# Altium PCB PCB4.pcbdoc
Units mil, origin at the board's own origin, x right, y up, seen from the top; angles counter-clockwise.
Board outline 1779.17 x 1753.12 mil, 2 copper layers (Top Layer, Bottom Layer); 24 components, 31 nets, 113 pads, 26 vias.
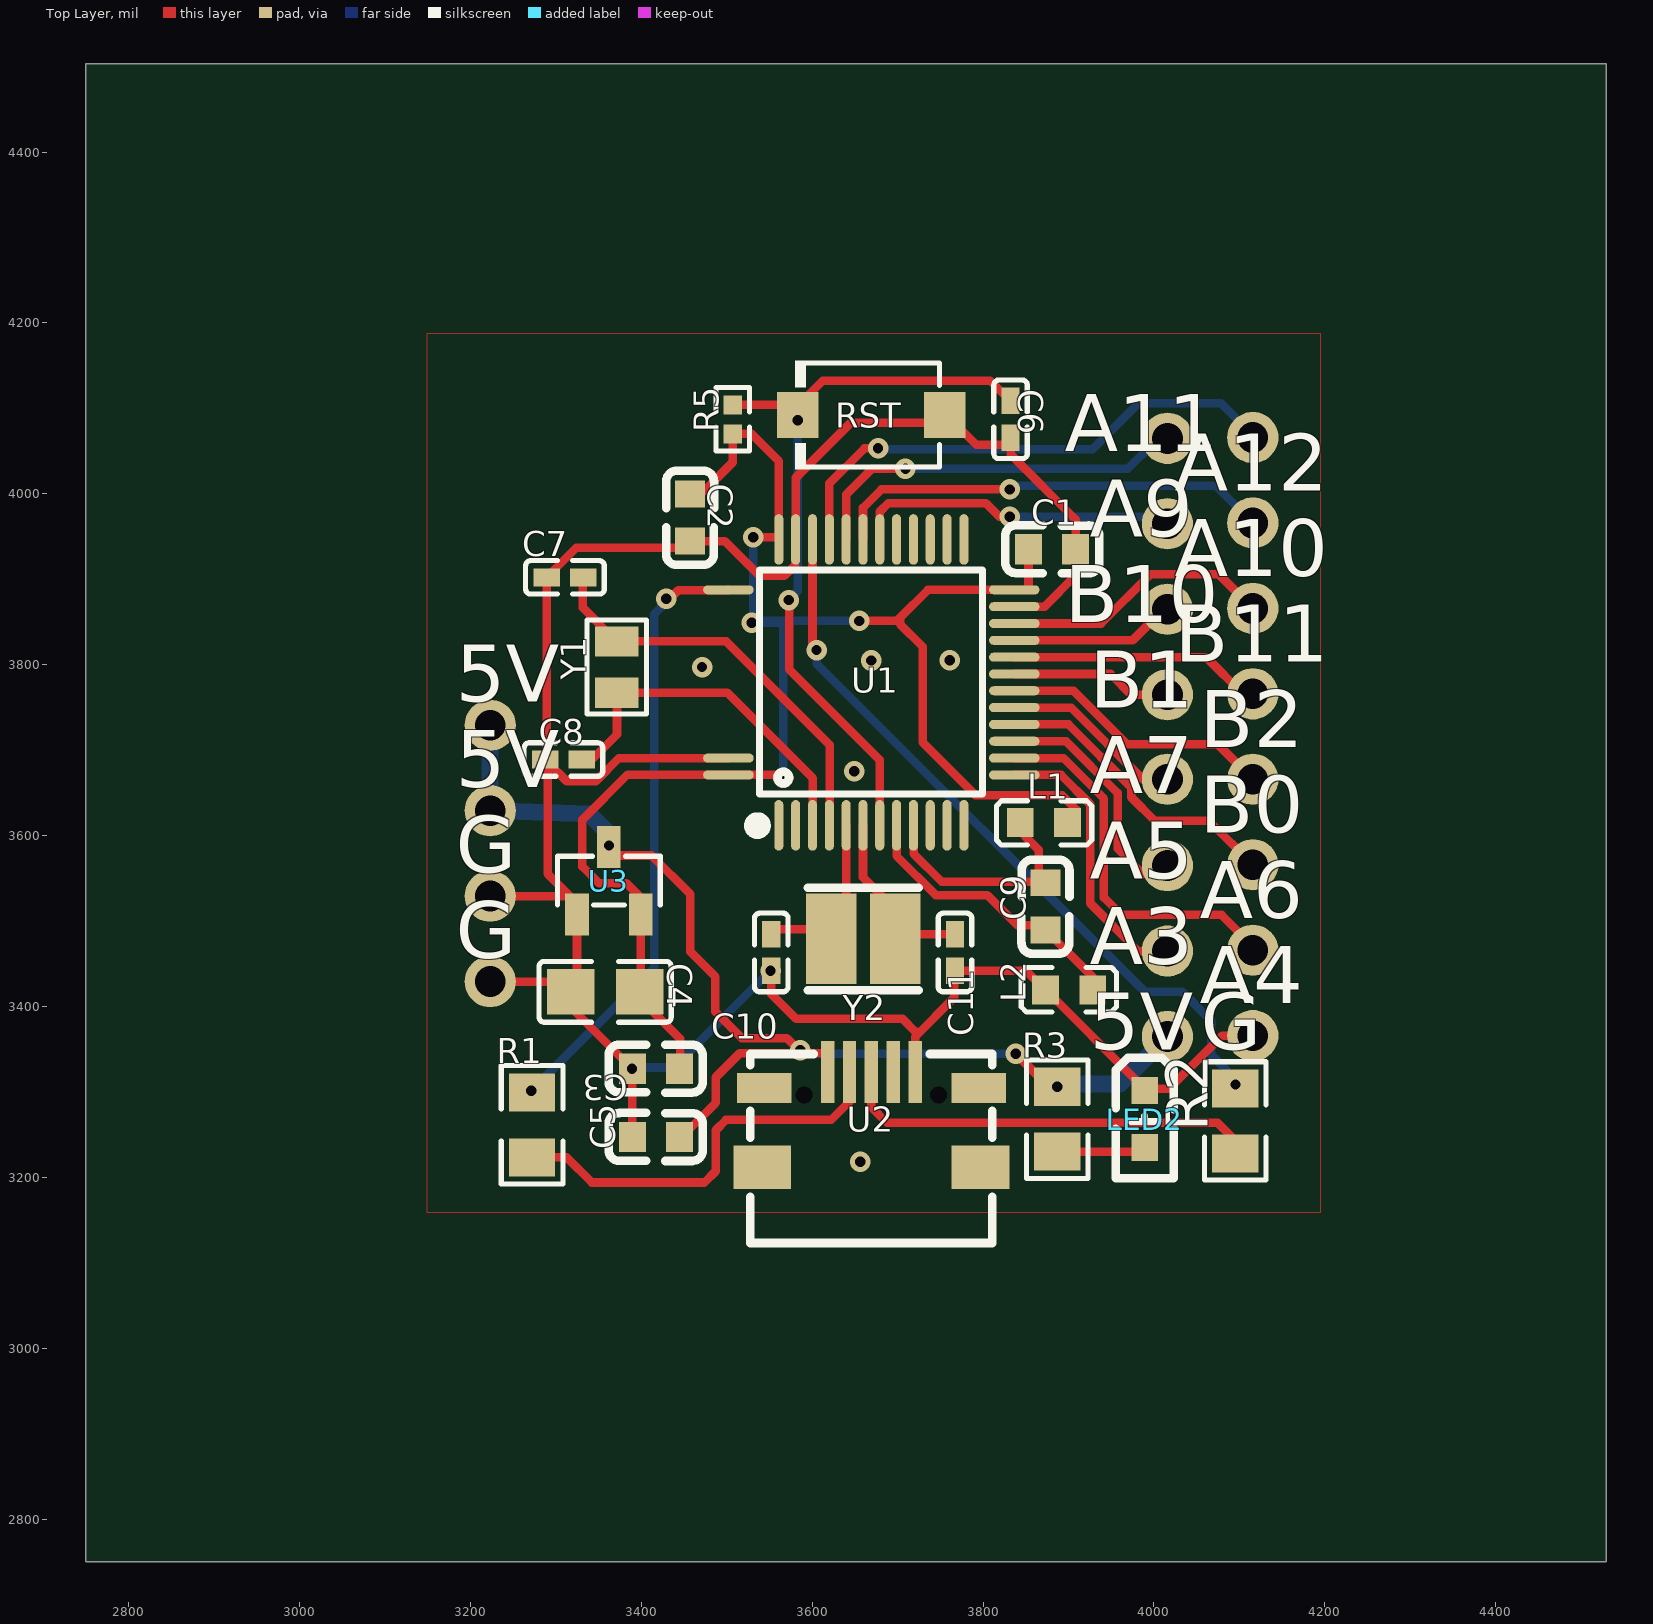
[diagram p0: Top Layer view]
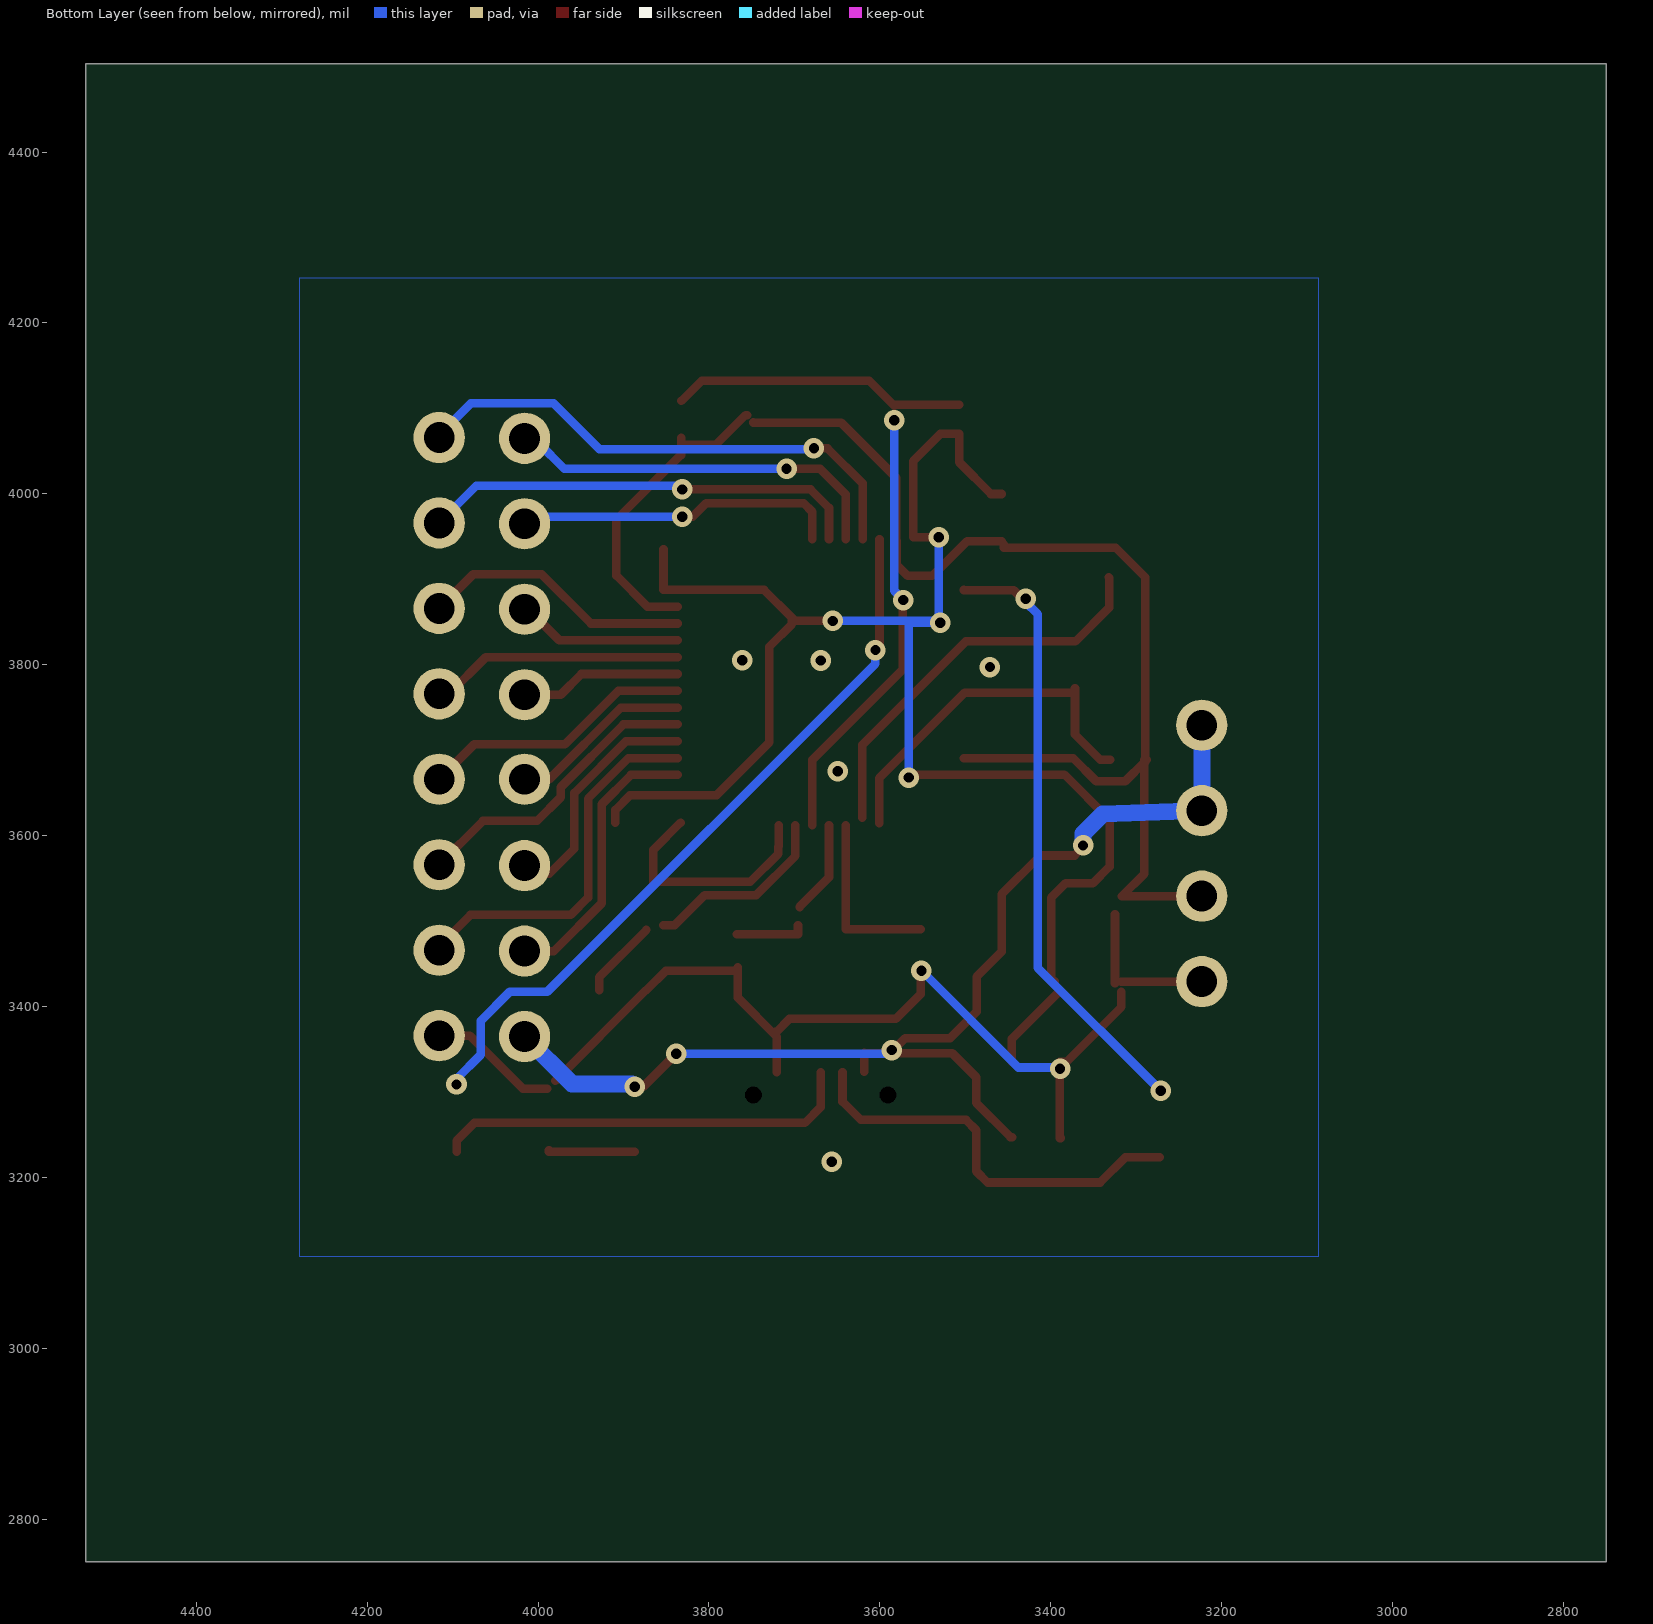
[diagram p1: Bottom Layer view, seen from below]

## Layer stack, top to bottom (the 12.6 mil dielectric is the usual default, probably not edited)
Top Solder: solder mask 0.4, Solder Resist, Dk 3.5
Top Layer: signal copper 1.4
Dielectric 1: dielectric 12.6, FR-4, Dk 4.8
Bottom Layer: signal copper 1.4
Bottom Solder: solder mask 0.4, Solder Resist, Dk 3.5

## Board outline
4529.17,2750 2750,2750 2750,4503.12 4529.17,4503.12

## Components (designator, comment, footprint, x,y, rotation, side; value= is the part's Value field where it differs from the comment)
C1 "" c0603_1 3880.75,3935.15 r180 top
C2 "" c0603_1 3457.15,3972.15 r90 top
C3 "" c0603_1 3417.15,3327.15 r0 top
C4 "" c0805 3357.72,3417.15 r0 top
C5 "" c0603_1 3417.15,3247.15 r0 top
C6 "" c0402_1 3832.15,4087.15 r270 top
C7 "" c0402_1 3310.65,3902.15 r180 top
C8 "" c0402_1 3308.94,3688.98 r180 top
C9 "" c0603_1 3873.15,3517.15 r90 top
C10 "" c0402_1 3552.15,3463.16 r270 top
C11 "" c0402_1 3767.15,3463.16 r270 top
L1 "" l0603 3871.15,3615.15 r180 top
L2 "" l0603 3900.75,3419.15 r0 top
LED2 "" led0603-r-rd_1 3989.24,3268.22 r270 top
R1 "" r0805 3272.15,3261.45 r90 top
R2 "" r0805 4095.18,3266.02 r90 top
R3 "" r0805 3886.79,3268.02 r90 top
R5 "" r0402_1 3507.15,4087.15 r270 top
RST "" sw-smd_l3.9-w3.0-p4.45 3669.28,4092.15 r180 top
U1 "" lqfp-48_l7.0-w7.0-p0.50-ls9.0-bl_4 3669.28,3779.28 r0 top
U2 "" micro-usb-smd_micro-qtzb5.0 3669.28,3267.56 r0 top
U3 "" sot-23-3_l2.9-w1.3-p1.90-ls2.4-br 3362.15,3547.15 r270 top
Y1 "" crystal-smd_l2.0-w1.2 3371.15,3797.15 r90 top
Y2 "" osc-smd_2p-l3.2-w2.5 3659.75,3479.15 r180 top

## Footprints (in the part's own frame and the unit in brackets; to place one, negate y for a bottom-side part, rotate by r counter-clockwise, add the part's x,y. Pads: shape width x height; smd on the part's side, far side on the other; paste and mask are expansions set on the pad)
c0402_1 [mil]
  rect 31.1x21.3 smd: 1(-21.5,0) 2(21.5,0)
  silkscreen extent -46,-20 46,20
c0603_1 [mil]
  rect 31.5x35.4 smd: 1(-27.6,0) 2(27.6,0)
  silkscreen extent -55,-28 55,28
c0805 [mil]
  rect 55.5x53.2 smd: 1(-40.5,0) 2(40.6,0)
  silkscreen extent -77,-36 77,36
crystal-smd_l2.0-w1.2 [mil]
  rect 35.4x51.2 smd: 1(-30,0) 2(30,0)
  silkscreen extent -55,-35 55,35
l0603 [mil]
  rect 31.5x34 smd: 1(-27.6,0) 2(27.6,0)
  silkscreen extent -56,-26 56,26
led0603-r-rd_1 [mil]
  rect 31.5x31.5 smd: 1(33.5,0) 2(-33.5,0)
  silkscreen extent -72,-34 70,34
lqfp-48_l7.0-w7.0-p0.50-ls9.0-bl_4 [mil]
  oval 10.6x59.1 smd: 1(-108.3,-167.3) 2(-88.6,-167.3) 3(-68.9,-167.3) 4(-49.2,-167.3) 5(-29.5,-167.3) 6(-9.8,-167.3) 7(9.8,-167.3) 8(29.5,-167.3) 9(49.2,-167.3) 10(68.9,-167.3) 11(88.6,-167.3) 12(108.3,-167.3) 25(108.3,167.3) 26(88.6,167.3) 27(68.9,167.3) 28(49.2,167.3) 29(29.5,167.3) 30(9.8,167.3) 31(-9.8,167.3) 32(-29.5,167.3) 33(-49.2,167.3) 34(-68.9,167.3) 35(-88.6,167.3) 36(-108.3,167.3)
  oval 59.1x10.6 smd: 13(167.3,-108.3) 14(167.3,-88.6) 15(167.3,-68.9) 16(167.3,-49.2) 17(167.3,-29.5) 18(167.3,-9.8) 19(167.3,9.8) 20(167.3,29.5) 21(167.3,49.2) 22(167.3,68.9) 23(167.3,88.6) 24(167.3,108.3) 37(-167.3,108.3) 47(-167.3,-88.6) 48(-167.3,-108.3)
  silkscreen extent -141,-176 130,132
micro-usb-smd_micro-qtzb5.0 [mil]
  rect 15.7x72.8 smd: 1(-51.2,55.8) 2(-25.6,55.8) 3(0,55.8) 4(25.6,55.8) 5(51.2,55.8)
  rect 67.5x51.2 smd: 6(-127.7,-55.8) 6(127.7,-55.8)
  rect 64x35.4 smd: 6(-125.5,37.1) 6(125.5,37.1)
  Multi-Layer board cut-out: -68.9,28.8 -69.87,33.05 -72.59,36.46 -76.52,38.35 -80.88,38.35 -84.81,36.46 -87.53,33.05 -88.5,28.8 -88.5,28.8 -87.53,24.55 -84.81,21.14 -80.88,19.25 -76.52,19.25 -72.59,21.14 -69.87,24.55 -68.9,28.8
  Multi-Layer board cut-out: 88.5,28.8 87.53,33.05 84.81,36.46 80.88,38.35 76.52,38.35 72.59,36.46 69.87,33.05 68.9,28.8 68.9,28.8 69.87,24.55 72.59,21.14 76.52,19.25 80.88,19.25 84.81,21.14 87.53,24.55 88.5,28.8
  silkscreen extent -142,-144 142,77
osc-smd_2p-l3.2-w2.5 [mil]
  rect 59.1x106.3 smd: 1(37.4,0) 2(-37.4,0)
  silkscreen extent -65,-60 65,60
r0402_1 [mil]
  rect 22.3x21.3 smd: 1(-17,0) 2(17,0)
  silkscreen extent -37,-20 37,20
r0805 [mil]
  rect 44.6x54.2 smd: 1(-38,0) 2(38,0)
  silkscreen extent -69,-36 69,36
sot-23-3_l2.9-w1.3-p1.90-ls2.4-br [mil]
  rect 49.2x27.6 smd: 1(39.4,-37.4) 2(39.4,37.4) 3(-39.4,0)
  silkscreen extent -29,-60 29,60
sw-smd_l3.9-w3.0-p4.45 [mil]
  rect 48.4x53.5 smd: 1(-86,0) 2(86,0)
  silkscreen extent -80,-64 89,64

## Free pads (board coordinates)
  round 60 hole 36: ""(3223.15,3429.15) ""(3223.15,3529.15) ""(3223.15,3629.15) ""(3223.15,3729.15) ""(4015.73,3364.85) ""(4015.73,3464.85) ""(4015.73,3564.85) ""(4015.73,3665.85) ""(4015.73,3764.85) ""(4015.73,3864.85) ""(4015.73,3964.85) ""(4015.73,4064.85) ""(4115.73,3365.85) ""(4115.73,3465.85) ""(4115.73,3565.85) ""(4115.73,3665.85) ""(4115.73,3765.85) ""(4115.73,3865.85) ""(4115.73,3965.85) ""(4115.73,4065.85)

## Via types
v1: diameter 24.02, hole 12.01, Top Layer to Bottom Layer, 26 vias

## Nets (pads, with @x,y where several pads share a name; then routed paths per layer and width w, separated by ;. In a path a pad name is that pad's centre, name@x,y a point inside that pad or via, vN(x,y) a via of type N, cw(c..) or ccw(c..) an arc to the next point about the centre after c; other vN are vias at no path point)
3V3: C1.2 C2.2 C3.2 C4.2 L1.1 R5.2 U1.24 U1.36 U1.48 U3.2 | length 1975.9
  Top Layer w10: C4.2@3390.32,3417.15 3445.34,3362.14 C3.2@3445.34,3335.32 ; C4.2@3395.22,3429.33 3399.55,3429.33 U3.2 3399.55,3527.18 3382.54,3544.19 3350.55,3544.19 3331.08,3563.66 3331.08,3618.56 3383.89,3671.37 3501.58,3671.37 U1.48 3566.18,3670.98 v1(3566.18,3667.88) ; C2.2 3470.03,3999.75 3507.15,4036.87 R5.2@3507.15,4067.26 ; R5.2 3529.15,4070.15 3560.98,4038.32 3560.98,3949.15 v1(3531.15,3949.15) ; v1(3655.15,3851.15) 3699.15,3851.15 3703.15,3855.15 ; C1.2 3853.15,3887.58 U1.24 3735.58,3887.58 3703.15,3855.15 ; L1.1@3909.5,3615.15 3909.5,3630.08 3892.43,3647.15 3791.15,3647.15 3729.15,3709.15 3729.15,3821.15 3703.15,3847.15 3703.15,3855.15
  Bottom Layer w10: v1(3531.15,3949.15) v1@3531.15,3851.15 ; v1(3566.18,3667.88) 3566.18,3849.15 v1(3529.15,3849.15) v1@3531.15,3851.15 ; v1(3655.15,3851.15) v1@3531.15,3851.15
  other v1: 3531.15,3949.15
$3N994: C6.1 R5.1 RST.2 U1.7 | length 868
  Top Layer w10: R5.1 3583.28,4104.15 3583.28,4103.28 3612.15,4132.15 3808.65,4132.15 C6.1 ; v1@3573.17,3873.68 3573.17,3794.38 3679.08,3688.48 U1.7
  Bottom Layer w10: v1(3572.5,3875.6) 3572.5,3875.96 3583.07,3886.53 v1(3583.07,4086.09)
$3N1484: C10.1 U1.5 Y2.1 | length 209.3
  Top Layer w10: C10.1@3552.15,3490.27 3639.78,3490.27 U1.5
$3N1487: C11.1 U1.6 Y2.2 | length 192
  Top Layer w10: U1.6 3659.48,3551.23 3693.81,3516.9 Y2.2@3693.81,3516.12 ; Y2.2@3695.76,3495.15 3695.76,3484.66 C11.1
$3N2325: C7.1 U1.4 Y1.2 | length 476.3
  Top Layer w10: C7.1 3331.72,3901.72 3331.72,3866.58 Y1.2 3499.5,3827.15 3620.65,3706 U1.4@3620.65,3620.89
$3N2326: C8.1 U1.3 Y1.1 | length 431.2
  Top Layer w10: C8.1 3342.17,3688.98 3371.59,3718.39 Y1.1@3371.59,3767.15 ; Y1.1 Y1.1@3371.59,3767.15 ; Y1.1@3371.59,3772.37 Y1.1@3371.59,3767.15 ; U1.3@3600.9,3614.31 3600.9,3666.98 3500.73,3767.15 Y1.1@3371.59,3767.15
$3N4005: R1.1 U2.2 | length 485.3
  Top Layer w10: R1.1 3312.65,3223.45 3342.15,3193.95 3473.95,3193.95 3487.15,3207.15 3487.15,3255.15 3499.15,3267.15 3622.08,3267.15 3643.68,3288.74 U2.2@3643.68,3322.95
$3N4016: R2.1 U2.3 | length 496
  Top Layer w10: U2.3@3669.28,3322.95 3669.28,3282.09 3687.72,3263.65 4074.61,3263.65 4095.18,3243.08 R2.1@4095.18,3230.02
$3N7646: LED2.1 R3.1 | length 102
  Top Layer w10: R3.1 3987.19,3230.02 LED2.1@3987.19,3231.58
+5V: C5.2 pad.@3223.15,3629.15 pad.@3223.15,3729.15 pad.@4015.73,3364.85 R3.2 U2.1 U3.3 | length 1372.6
  Top Layer w10: U3.3 3372.04,3576.66 3412.12,3576.66 3457.48,3531.3 3457.48,3463.99 3486.74,3434.73 3486.74,3393.76 3517.47,3363.03 3570.23,3363.03 v1@3587.74,3345.52 ; C5.2 3447.15,3247.15 3487.15,3287.15 3487.15,3317.15 3515.33,3345.33 v1@3586.03,3345.33 ; U2.1 3618.16,3323.45 3618.16,3345.52 v1@3587.93,3345.33 ; v1@3843.01,3339.9 3876.88,3306.02 v1(3886.79,3306.02) 3887.29,3306.02 R3.2@3887.29,3305.9 ; v1@3586.03,3345.33 v1@3587.74,3345.52 ; v1@3586.03,3345.33 v1@3587.74,3345.33 ; v1@3587.74,3345.33 v1@3587.93,3345.33 ; v1@3587.74,3345.33 v1@3587.93,3345.33 ; v1@3587.74,3345.52 v1@3587.93,3345.33
  Bottom Layer w10: v1@3589.02,3349.05 3589.02,3344.74 v1(3838.34,3344.74)
  Bottom Layer w20: pad.@3223.15,3729.15 3223.15,3629.15 3339.15,3625.15 3362.15,3602.15 v1(3362.15,3588.45) ; v1(3886.79,3306.02) 3889.91,3309.15 3960.03,3309.15 pad.@4015.73,3364.85
  other v1: 3586.03,3349
GND: C1.1 C2.1 C3.1 C4.1 C5.1 C6.2 C7.2 C8.2 C10.2 C11.2 L2.1 LED2.2 pad.@3223.15,3429.15 pad.@3223.15,3529.15 pad.@4115.73,3365.85 RST.1 U1.23 U1.35 U1.47 U2.5 U3.1 | length 3082.5
  Top Layer w10: pad.@3223.15,3429.15 C4.1@3317.22,3429.15 ; pad.@3223.15,3529.15 3316.62,3529.15 3290.36,3555.41 C8.2@3290.36,3685.94 ; C8.2@3290.36,3687.04 C8.2@3290.36,3685.94 ; C4.1 3317.22,3399.48 3381.55,3335.15 3389.28,3335.15 3389.55,3327.14 3389.55,3246.07 C5.1@3388.27,3246.07 ; C4.1@3324.75,3427.38 U3.1 ; C2.1@3455.14,3940.72 3455.14,3937.06 3324.06,3937.06 C7.2 3289.38,3902.15 C8.2@3289.38,3685.94 ; C2.1 3497.87,3944.55 3538.55,3903.88 3567.26,3903.88 3580.38,3916.99 U1.35@3580.38,3945.12 ; U1.47 3373.9,3690.68 3346.81,3663.59 3312.84,3663.59 C8.2@3290.36,3686.06 ; C10.2 3552.15,3414.52 3581.09,3385.58 3705.71,3385.58 3721.07,3370.21 3722.17,3370.21 ; U1.35 3580.68,4018.68 3645.15,4083.15 3747.9,4083.15 RST.1@3747.9,4083.81 ; U2.5@3720.48,3322.95 3720.77,3323.24 3720.77,3364.73 3766.13,3410.09 C11.2@3766.13,3445.93 ; RST.1 3757.15,4092.15 3792.15,4057.15 C6.2@3832.15,4057.15 ; C11.2 3850.64,3441.66 L2.1 3873.51,3419.15 LED2.2@3979.75,3312.91 ; C6.2 C6.2@3832.15,4057.15 ; U1.23 3871.88,3867.88 3908.35,3904.35 C1.1 3908.35,3969.95 3833.15,4045.15 3832.15,4045.15 C6.2@3832.15,4057.15 ; LED2.2@3989.24,3303.72 4017.72,3303.72 4079.85,3365.85 pad.@4115.73,3365.85 ; C8.2@3289.38,3685.94 C8.2@3289.38,3688.98 ; C8.2@3289.38,3685.94 C8.2@3289.38,3687.04 ; C8.2@3289.38,3687.04 C8.2 C8.2@3289.38,3688.98 ; C8.2@3289.38,3687.04 C8.2@3290.36,3686.06 ; C8.2@3289.38,3688.98 3290.36,3688.98 C8.2@3290.36,3685.94 ; C8.2@3290.36,3685.94 C8.2@3290.36,3686.06
  Bottom Layer w10: v1@3393.9,3328.54 3437.98,3328.54 v1(3551.34,3441.9)
  other v1: 3656.11,3218.36 3389,3327.14 3649.15,3675.15 3471.15,3797.15 3669.28,3804.88 3761.15,3805.15
PA3: pad.@4015.73,3464.85 U1.13 | length 332.4
  Top Layer w10: U1.13 3891.23,3670.98 3925.5,3636.71 3925.5,3520.8 3981.45,3464.85 pad.@4015.73,3464.85
PA4: pad.@4115.73,3465.85 U1.14 | length 442.9
  Top Layer w10: U1.14 3894.16,3690.68 3941.5,3643.33 3941.5,3527.43 3961.78,3507.15 4079.15,3507.15 4115.73,3470.57 pad.@4115.73,3465.85
PA5: pad.@4015.73,3564.85 U1.15 | length 291.3
  Top Layer w10: U1.15 3897.09,3710.38 3957.5,3649.96 3957.5,3584.8 3987.15,3555.15 4015.73,3555.15 pad.@4015.73,3564.85
PA6: pad.@4115.73,3565.85 U1.16 | length 354.1
  Top Layer w10: U1.16 3900.01,3730.08 3973.5,3656.59 3973.5,3644.8 4001.15,3617.15 4064.43,3617.15 pad.@4115.73,3565.85
PA7: pad.@4015.73,3665.85 U1.17 | length 213.9
  Top Layer w10: U1.17 3902.94,3749.78 3986.87,3665.85 pad.@4015.73,3665.85
PA9: pad.@4015.73,3964.85 U1.30 | length 371.7
  Top Layer w10: U1.30 3679.08,3979.08 3689.15,3989.15 3803.15,3989.15 3819.15,3973.15 v1(3831.15,3973.15)
  Bottom Layer w10: v1(3831.15,3973.15) pad.@4007.43,3973.15
PA10: pad.@4115.73,3965.85 U1.31 | length 520.9
  Top Layer w10: U1.31 3659.48,3983.48 3681.15,4005.15 v1@3829.15,4005.15
  Bottom Layer w10: v1(3831.15,4005.15) 3831.15,4007.15 3835.15,4007.15 3837.15,4009.15 4072.43,4009.15 pad.@4115.73,3965.85
PA11: pad.@4015.73,4064.85 U1.32 | length 435.6
  Top Layer w10: U1.32 3639.78,3999.15 3669.78,4029.15 v1(3709.15,4029.15)
  Bottom Layer w10: v1@3711.15,4029.15 3969.15,4029.15 pad.@3999.73,4059.73
PA12: pad.@4115.73,4065.85 U1.33 | length 618.6
  Top Layer w10: U1.33 3620.08,4012.08 3661.15,4053.15 v1(3677.15,4053.15)
  Bottom Layer w10: v1@3679.15,4047.15 3684.16,4052.16 3928.16,4052.16 3981.85,4105.85 4078.45,4105.85 4115.73,4068.57 pad.@4115.73,4065.85
PA13: R2.2 U1.34 | length 871.4
  Top Layer w10: U1.34 3600.38,3817.15 v1(3605.15,3817.15)
  Bottom Layer w10: v1(3605.15,3817.15) 3605.15,3801.15 3989.15,3417.15 4033.15,3417.15 4067.15,3383.15 4067.15,3343.42 4095.42,3315.15 v1(4095.42,3308.77)
PA14: R1.2 U1.37 | length 718.4
  Top Layer w10: v1(3429.15,3877.15) 3433.15,3877.15 3443.19,3887.19 3501.59,3887.19 U1.37
  Bottom Layer w10: v1(3271.27,3301.25) 3415.15,3445.13 3415.15,3859.15 3429.15,3873.15 v1(3429.15,3877.15)
PB0: pad.@4115.73,3665.85 U1.18 | length 322.1
  Top Layer w10: U1.18 3905.87,3769.48 3968.49,3706.85 4074.73,3706.85 pad.@4115.73,3665.85
PB1: pad.@4015.73,3764.85 U1.19 | length 189.2
  Top Layer w10: U1.19 3949.22,3789.08 3973.45,3764.85 pad.@4015.73,3764.85
PB2: pad.@4115.73,3765.85 U1.20 | length 296.9
  Top Layer w10: U1.20 4061.15,3808.78 4104.08,3765.85 pad.@4115.73,3765.85
PB10: pad.@4015.73,3864.85 U1.21 | length 194.2
  Top Layer w10: U1.21 3975.15,3828.48 4011.52,3864.85 pad.@4015.73,3864.85
PB11: pad.@4115.73,3865.85 U1.22 | length 319.6
  Top Layer w10: U1.22 3938.18,3848.18 3995.85,3905.85 4075.73,3905.85 pad.@4115.73,3865.85
VBAT: U1.1
VDDA: C9.2 L1.2 U1.9 | length 275.6
  Top Layer w10: U1.9 3718.48,3587.3 3718.72,3587.06 3718.72,3578.8 3751.45,3546.07 3865.15,3546.07 3865.15,3583.15 L1.2@3833.15,3615.15
VSSA: C9.1 L2.2 U1.8 | length 317
  Top Layer w10: U1.8 3698.78,3576.11 3744.82,3530.07 3805.13,3530.07 3840.06,3495.15 3853.15,3495.15 ; C9.1 3928.35,3434.35 L2.2
"": U1.2 U1.10 U1.11 U1.12 U1.25 U1.26 U1.27 U1.28 U1.29 U2.4 U2.6

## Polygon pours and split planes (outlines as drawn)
GND on Top Layer (solid, remove dead copper, pour order 0): 3149.16,3159.15 4195.14,3159.15 4195.14,4187.14 3149.16,4187.14
GND on Bottom Layer (solid, remove dead copper, pour order 1): 3087.16,3107.13 4279.17,3107.13 4279.17,4253.12 3087.16,4253.12

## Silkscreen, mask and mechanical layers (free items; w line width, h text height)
Top Overlay:
  text "A11" at 3895.7,4049.49 h66.9
  text "A12" at 4024.17,4003.49 h66.9
  text "A9" at 3925.06,3949.49 h66.9
  text "A10" at 4024.17,3903.49 h66.9
  text "B10" at 3895.7,3849.49 h66.9
  text "B11" at 4024.17,3803.49 h66.9
  text "5V" at 3183.06,3756.49 h66.9
  text "B1" at 3925.06,3749.49 h66.9
  text "B2" at 4053.53,3703.49 h66.9
  text "5V" at 3183.06,3656.49 h66.9
  text "A7" at 3925.06,3649.49 h66.9
  text "B0" at 4053.53,3603.49 h66.9
  text "G" at 3182.89,3556.49 h66.9
  text "A5" at 3925.06,3549.49 h66.9
  text "A6" at 4053.53,3503.49 h66.9
  text "G" at 3182.89,3456.49 h66.9
  text "A3" at 3925.06,3449.49 h66.9
  text "A4" at 4053.53,3403.49 h66.9
  text "5V" at 3925.06,3349.49 h66.9
  text "G" at 4054.89,3349.49 h66.9
Mechanical 1:
  lines w10 net "": 3177.15,3177.15 3177.15,4161.4 4161.4,3177.15 3177.15,3177.15 ; 3177.15,4163.6 4161.4,4163.6 4161.4,3179.34 3177.15,4163.6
